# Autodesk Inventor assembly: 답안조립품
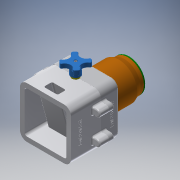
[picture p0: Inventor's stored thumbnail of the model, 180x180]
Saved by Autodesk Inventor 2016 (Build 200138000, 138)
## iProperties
Created: 2018-01
Part Number: 답안조립품
Material: 일반
Document SubType Name: Assembly
Designer: 605-03
Author: 605-03
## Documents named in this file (9)
- C:\Users\605-03\Desktop\480107V1010\답안조립품.iam
- C:\Users\605-03\Desktop\480107V1010\본체.ipt
- C:\Users\605-03\Desktop\480107V1010\본체커버.ipt
- C:\Users\605-03\Desktop\480107V1010\볼트 M3x12.ipt
- C:\Users\605-03\Desktop\480107V1010\볼트 M4x12.ipt
- C:\Users\605-03\Desktop\480107V1010\용기.ipt
- C:\Users\605-03\Desktop\480107V1010\용기캡.ipt
- C:\Users\605-03\Desktop\480107V1010\핸들.ipt
- C:\Users\605-03\Desktop\480107V1010\핸들축.ipt
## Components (2 placed, 2 different names)
1. 핸들:1
2. 핸들축:1
